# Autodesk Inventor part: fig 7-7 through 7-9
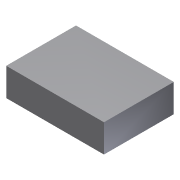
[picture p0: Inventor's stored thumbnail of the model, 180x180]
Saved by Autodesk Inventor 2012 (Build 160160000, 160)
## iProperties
Created: 2009-09
Part Number: fig 7-7 through 7-9
Document SubType Name: Modeling
Designer: Sham
Density: 1 g/cm^3
Material: Default
Author: Sham
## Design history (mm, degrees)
sketch "Sketch1"
  geometry: L1 (-28, 20)-(0, 20); L2 (0, 20)-(0, 0); L3 (0, 0)-(-28, 0); L4 (-28, 0)-(-28, 20)
  constraints: 8 end point, 2 parallel, 1 horizontal, 1 perpendicular
extrude "Extrusion1" new body sketch "Sketch1" distance "d0" = 8; taper "d1" = 0 deg
body "Solid1"
